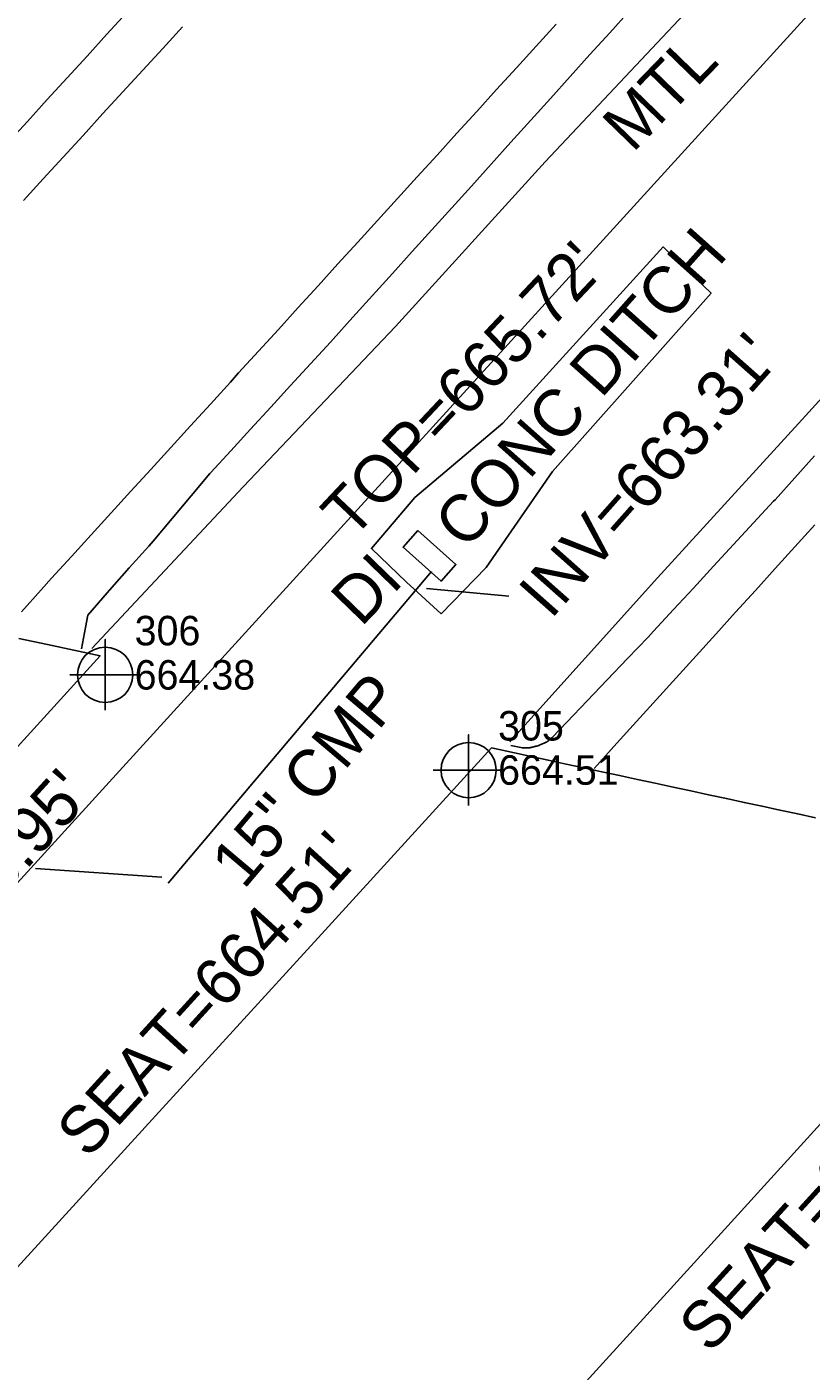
# Model space of a CAD drawing. Extents: x 1806071 to 1809844, y 912722 to 917035.
# Drawn here: x 1809158.4 to 1809224.9, y 916067.4 to 916181.4 of the extents above; entities that cross this region are included whole.
import ezdxf

# ---------------------------------------------------------------- set-up
doc = ezdxf.new("R2010")
doc.units = 0
for name, color, linetype in [('Exist Guardrail', 7, 'Continuous'), ('Exist Guardrail Text', 7, 'Continuous'), ('Exist Horizontal Alignment', 7, 'Continuous'), ('Exist Roads EOP', 7, 'Continuous'), ('Exist Roads EOT', 7, 'Continuous'), ('Exist Structure Major Bridge Seat Cogo Elevation', 7, 'Continuous'), ('Exist Structure Major Bridge Seat Cogo Number', 7, 'Continuous'), ('Exist Structure Major Bridge Seat Cogo Point CELL', 7, 'Continuous'), ('Exist Structure Major Bridge Seat Top Elevation', 7, 'Continuous'), ('Exist Structure Major Deck Tunnel Box Culvert', 7, 'Continuous'), ('Exist Structure Minor Drop Inlet', 7, 'Continuous'), ('Exist Structure Minor Drop Inlet Text', 7, 'Continuous'), ('Exist Structure Minor Drop Inlet Top Elevation', 7, 'Continuous'), ('Exist Structure Minor Paved Ditch or Gutter', 7, 'Continuous'), ('Exist Structure Minor Paved Ditch or Gutter Text', 7, 'Continuous'), ('Exist Structure Minor Pipes CMP 15 Inch', 7, 'Continuous'), ('Exist Structure Minor Pipes CMP 15 Inch Invert', 7, 'Continuous'), ('Exist Structure Minor Pipes CMP 15 Inch Text', 7, 'Continuous')]:
    doc.layers.add(name, color=color, linetype=linetype)

msp = doc.modelspace()

# ---------------------------------------------------------------- linework, layer by layer
at = {"layer": 'Exist Guardrail'}
for points in [[(1809223.66, 916192.6), (1809202.38, 916169.96), (1809189.69, 916156.01), (1809176.75, 916142.41), (1809163.93, 916128.69)], [(1809199.38, 916120.79), (1809211.9, 916134.7), (1809224.46, 916148.44), (1809245.44, 916171.5)]]:
    msp.add_lwpolyline(points, dxfattribs=at)
at = {"layer": 'Exist Horizontal Alignment'}
msp.add_line((1806073.69, 912724.84), (1809374.2, 916346.52), dxfattribs=at)
at = {"layer": 'Exist Roads EOP'}
for points in [[(1809166.88, 916182.62), (1809165.19, 916180.78), (1809163.51, 916178.93), (1809161.82, 916177.08), (1809160.14, 916175.24), (1809158.45, 916173.39), (1809156.76, 916171.55)], [(1809163.05, 916128.67), (1809163.39, 916130.49), (1809163.59, 916131.52), (1809165.21, 916133.42), (1809165.42, 916133.66), (1809167.09, 916135.53), (1809168.76, 916137.39), (1809169.13, 916137.8), (1809170.73, 916139.72), (1809172.34, 916141.64), (1809173.94, 916143.55), (1809174.01, 916143.63), (1809175.7, 916145.47), (1809177.39, 916147.31), (1809179.09, 916149.15), (1809180.78, 916150.99), (1809182.47, 916152.83), (1809184.16, 916154.67), (1809184.39, 916154.93), (1809186.07, 916156.78), (1809187.74, 916158.64), (1809189.42, 916160.49), (1809191.09, 916162.35), (1809192.77, 916164.2), (1809194.45, 916166.06), (1809196.12, 916167.91), (1809197.8, 916169.77), (1809199.47, 916171.63), (1809201.15, 916173.48), (1809202.82, 916175.34), (1809204.5, 916177.19), (1809206.17, 916179.05), (1809207.85, 916180.9), (1809209.52, 916182.76)], [(1809225.22, 916145.04), (1809223.54, 916143.18), (1809221.87, 916141.32), (1809221.74, 916141.18), (1809220.05, 916139.35), (1809218.35, 916137.51), (1809216.66, 916135.67), (1809214.96, 916133.83), (1809213.27, 916132), (1809211.57, 916130.16), (1809211.1, 916129.65), (1809209.37, 916127.85), (1809207.64, 916126.04), (1809205.94, 916124.27), (1809204.22, 916122.46), (1809202.96, 916121.15), (1809202.95, 916121.14), (1809202.95, 916121.14), (1809202.95, 916121.14), (1809202.94, 916121.13), (1809202.94, 916121.13), (1809202.93, 916121.13), (1809202.93, 916121.13), (1809202.93, 916121.12), (1809202.92, 916121.12), (1809202.92, 916121.12), (1809202.92, 916121.11), (1809202.91, 916121.11), (1809202.91, 916121.11), (1809202.91, 916121.1), (1809202.9, 916121.1), (1809202.9, 916121.1), (1809202.89, 916121.09), (1809202.89, 916121.09), (1809202.89, 916121.09), (1809202.88, 916121.09), (1809202.88, 916121.08), (1809202.88, 916121.08), (1809202.87, 916121.08), (1809202.87, 916121.07), (1809202.87, 916121.07), (1809202.86, 916121.07), (1809202.86, 916121.06), (1809202.85, 916121.06), (1809202.85, 916121.06), (1809202.85, 916121.05), (1809202.84, 916121.05), (1809202.84, 916121.05), (1809202.84, 916121.05), (1809202.83, 916121.04), (1809202.83, 916121.04), (1809202.82, 916121.04), (1809202.82, 916121.03), (1809202.82, 916121.03), (1809202.81, 916121.03), (1809202.81, 916121.02), (1809202.81, 916121.02), (1809202.8, 916121.02), (1809202.8, 916121.01), (1809202.8, 916121.01), (1809202.79, 916121.01), (1809202.79, 916121.01), (1809202.78, 916121), (1809202.78, 916121), (1809202.78, 916121), (1809202.77, 916120.99), (1809202.77, 916120.99), (1809202.77, 916120.99), (1809202.76, 916120.98), (1809202.76, 916120.98), (1809202.75, 916120.98), (1809202.75, 916120.98), (1809202.75, 916120.97), (1809202.74, 916120.97), (1809202.74, 916120.97), (1809202.74, 916120.96), (1809202.73, 916120.96), (1809202.73, 916120.96), (1809202.73, 916120.95), (1809202.72, 916120.95), (1809202.72, 916120.95), (1809202.71, 916120.94), (1809202.71, 916120.94), (1809202.71, 916120.94), (1809202.7, 916120.94), (1809202.7, 916120.93), (1809202.7, 916120.93), (1809202.69, 916120.93), (1809202.69, 916120.92), (1809202.68, 916120.92), (1809202.68, 916120.92), (1809202.68, 916120.91), (1809202.67, 916120.91), (1809202.67, 916120.91), (1809202.67, 916120.9), (1809202.66, 916120.9), (1809202.66, 916120.9), (1809202.66, 916120.9), (1809202.65, 916120.89), (1809202.65, 916120.89), (1809202.64, 916120.89), (1809202.64, 916120.88), (1809202.64, 916120.88), (1809202.63, 916120.88), (1809202.63, 916120.87), (1809202.63, 916120.87), (1809202.62, 916120.87), (1809202.62, 916120.86), (1809202.62, 916120.86), (1809202.61, 916120.86), (1809202.61, 916120.86), (1809202.6, 916120.85), (1809202.6, 916120.85), (1809202.6, 916120.85), (1809202.59, 916120.84), (1809202.59, 916120.84), (1809202.59, 916120.84), (1809202.58, 916120.83), (1809202.58, 916120.83), (1809202.57, 916120.83), (1809202.57, 916120.83), (1809202.57, 916120.82), (1809202.56, 916120.82), (1809202.56, 916120.82), (1809202.56, 916120.81), (1809202.55, 916120.81), (1809202.55, 916120.81), (1809202.55, 916120.8), (1809202.54, 916120.8), (1809202.54, 916120.8), (1809202.53, 916120.79), (1809202.53, 916120.79), (1809202.53, 916120.79), (1809202.52, 916120.79), (1809202.52, 916120.78), (1809202.52, 916120.78), (1809202.51, 916120.78), (1809202.51, 916120.77), (1809202.5, 916120.77), (1809202.49, 916120.77), (1809202.49, 916120.77), (1809202.48, 916120.76), (1809202.47, 916120.76), (1809202.47, 916120.76), (1809202.46, 916120.75), (1809202.46, 916120.75), (1809202.45, 916120.75), (1809202.44, 916120.75), (1809202.44, 916120.74), (1809202.43, 916120.74), (1809202.42, 916120.74), (1809202.42, 916120.74), (1809202.41, 916120.73), (1809202.4, 916120.73), (1809202.4, 916120.73), (1809202.39, 916120.73), (1809202.39, 916120.72), (1809202.38, 916120.72), (1809202.37, 916120.72), (1809202.37, 916120.71), (1809202.36, 916120.71), (1809202.35, 916120.71), (1809202.35, 916120.71), (1809202.34, 916120.7), (1809202.33, 916120.7), (1809202.33, 916120.7), (1809202.32, 916120.7), (1809202.31, 916120.69), (1809202.31, 916120.69), (1809202.3, 916120.69), (1809202.3, 916120.68), (1809202.29, 916120.68), (1809202.28, 916120.68), (1809202.28, 916120.68), (1809202.27, 916120.67), (1809202.26, 916120.67), (1809202.26, 916120.67), (1809202.25, 916120.67), (1809202.24, 916120.66), (1809202.24, 916120.66), (1809202.23, 916120.66), (1809202.23, 916120.65), (1809202.22, 916120.65), (1809202.21, 916120.65), (1809202.21, 916120.65), (1809202.2, 916120.64), (1809202.19, 916120.64), (1809202.19, 916120.64), (1809202.18, 916120.64), (1809202.17, 916120.63), (1809202.17, 916120.63), (1809202.16, 916120.63), (1809202.16, 916120.62), (1809202.15, 916120.62), (1809202.14, 916120.62), (1809202.14, 916120.62), (1809202.13, 916120.61), (1809202.12, 916120.61), (1809202.12, 916120.61), (1809202.11, 916120.61), (1809202.1, 916120.6), (1809202.1, 916120.6), (1809202.09, 916120.6), (1809202.08, 916120.59), (1809202.08, 916120.59), (1809202.07, 916120.59), (1809202.07, 916120.59), (1809202.06, 916120.58), (1809202.05, 916120.58), (1809202.05, 916120.58), (1809202.04, 916120.58), (1809202.03, 916120.57), (1809202.03, 916120.57), (1809202.02, 916120.57), (1809202.01, 916120.56), (1809202.01, 916120.56), (1809202, 916120.56), (1809202, 916120.56), (1809201.99, 916120.55), (1809201.98, 916120.55), (1809201.98, 916120.55), (1809201.97, 916120.55), (1809201.96, 916120.54), (1809201.96, 916120.54), (1809201.95, 916120.54), (1809201.94, 916120.53), (1809201.94, 916120.53), (1809201.93, 916120.53), (1809201.93, 916120.53), (1809201.92, 916120.52), (1809201.91, 916120.52), (1809201.91, 916120.52), (1809201.9, 916120.52), (1809201.89, 916120.51), (1809201.89, 916120.51), (1809201.88, 916120.51), (1809201.87, 916120.5), (1809201.87, 916120.5), (1809201.86, 916120.5), (1809201.85, 916120.5), (1809201.85, 916120.49), (1809201.84, 916120.49), (1809201.84, 916120.49), (1809201.83, 916120.49), (1809201.82, 916120.48), (1809201.82, 916120.48), (1809201.81, 916120.48), (1809201.8, 916120.48), (1809201.8, 916120.47), (1809201.79, 916120.47), (1809201.78, 916120.47), (1809201.78, 916120.46), (1809201.77, 916120.46), (1809201.77, 916120.46), (1809201.76, 916120.46), (1809201.75, 916120.45), (1809201.75, 916120.45), (1809201.74, 916120.45), (1809201.74, 916120.45), (1809201.73, 916120.45), (1809201.72, 916120.44), (1809201.72, 916120.44), (1809201.71, 916120.44), (1809201.71, 916120.44), (1809201.7, 916120.44), (1809201.7, 916120.44), (1809201.69, 916120.44), (1809201.68, 916120.43), (1809201.68, 916120.43), (1809201.67, 916120.43), (1809201.67, 916120.43), (1809201.66, 916120.43), (1809201.65, 916120.43), (1809201.65, 916120.43), (1809201.64, 916120.43), (1809201.64, 916120.42), (1809201.63, 916120.42), (1809201.63, 916120.42), (1809201.62, 916120.42), (1809201.61, 916120.42), (1809201.61, 916120.42), (1809201.6, 916120.42), (1809201.6, 916120.41), (1809201.59, 916120.41), (1809201.59, 916120.41), (1809201.58, 916120.41), (1809201.57, 916120.41), (1809201.57, 916120.41), (1809201.56, 916120.41), (1809201.56, 916120.4), (1809201.55, 916120.4), (1809201.55, 916120.4), (1809201.54, 916120.4), (1809201.53, 916120.4), (1809201.53, 916120.4), (1809201.52, 916120.4), (1809201.52, 916120.4), (1809201.51, 916120.39), (1809201.51, 916120.39), (1809201.5, 916120.39), (1809201.49, 916120.39), (1809201.49, 916120.39), (1809201.48, 916120.39), (1809201.48, 916120.39), (1809201.47, 916120.38), (1809201.46, 916120.38), (1809201.46, 916120.38), (1809201.45, 916120.38), (1809201.45, 916120.38), (1809201.44, 916120.38), (1809201.44, 916120.38), (1809201.43, 916120.37), (1809201.42, 916120.37), (1809201.42, 916120.37), (1809201.41, 916120.37), (1809201.41, 916120.37), (1809201.4, 916120.37), (1809201.4, 916120.37), (1809201.39, 916120.37), (1809201.38, 916120.36), (1809201.38, 916120.36), (1809201.37, 916120.36), (1809201.37, 916120.36), (1809201.36, 916120.36), (1809201.36, 916120.36), (1809201.35, 916120.36), (1809201.34, 916120.35), (1809201.34, 916120.35), (1809201.33, 916120.35), (1809201.33, 916120.35), (1809201.32, 916120.35), (1809201.31, 916120.35), (1809201.31, 916120.35), (1809201.3, 916120.34), (1809201.3, 916120.34), (1809201.29, 916120.34), (1809201.29, 916120.34), (1809201.28, 916120.34), (1809201.27, 916120.34), (1809201.27, 916120.34), (1809201.26, 916120.34), (1809201.26, 916120.33), (1809201.25, 916120.33), (1809201.25, 916120.33), (1809201.24, 916120.33), (1809201.23, 916120.33), (1809201.23, 916120.33), (1809201.22, 916120.33), (1809201.22, 916120.32), (1809201.21, 916120.32), (1809201.21, 916120.32), (1809201.2, 916120.32), (1809201.19, 916120.32), (1809201.19, 916120.32), (1809201.18, 916120.32), (1809201.18, 916120.31), (1809201.17, 916120.31), (1809201.17, 916120.31), (1809201.16, 916120.31), (1809201.15, 916120.31), (1809201.15, 916120.31), (1809201.14, 916120.31), (1809201.14, 916120.3), (1809201.13, 916120.3), (1809201.12, 916120.3), (1809201.12, 916120.3), (1809201.11, 916120.3), (1809201.11, 916120.3), (1809201.1, 916120.3), (1809201.1, 916120.3), (1809201.09, 916120.29), (1809201.08, 916120.29), (1809201.08, 916120.29), (1809201.07, 916120.29), (1809201.07, 916120.29), (1809201.06, 916120.29), (1809201.06, 916120.29), (1809201.05, 916120.28), (1809201.05, 916120.28), (1809201.04, 916120.28), (1809201.04, 916120.28), (1809201.03, 916120.28), (1809201.03, 916120.28), (1809201.02, 916120.28), (1809201.02, 916120.28), (1809201.01, 916120.28), (1809201.01, 916120.28), (1809201, 916120.28), (1809201, 916120.28), (1809200.99, 916120.28), (1809200.99, 916120.28), (1809200.98, 916120.28), (1809200.98, 916120.28), (1809200.97, 916120.28), (1809200.97, 916120.28), (1809200.96, 916120.28), (1809200.96, 916120.28), (1809200.95, 916120.28), (1809200.95, 916120.28), (1809200.94, 916120.28), (1809200.94, 916120.28), (1809200.93, 916120.28), (1809200.93, 916120.28), (1809200.92, 916120.28), (1809200.92, 916120.28), (1809200.91, 916120.28), (1809200.9, 916120.28), (1809200.9, 916120.28), (1809200.89, 916120.28), (1809200.89, 916120.28), (1809200.88, 916120.28), (1809200.88, 916120.28), (1809200.87, 916120.28), (1809200.87, 916120.28), (1809200.86, 916120.28), (1809200.86, 916120.28), (1809200.85, 916120.28), (1809200.85, 916120.28), (1809200.84, 916120.28), (1809200.84, 916120.28), (1809200.83, 916120.28), (1809200.83, 916120.28), (1809200.82, 916120.28), (1809200.82, 916120.28), (1809200.81, 916120.28), (1809200.81, 916120.28), (1809200.8, 916120.28), (1809200.8, 916120.28), (1809200.79, 916120.28), (1809200.79, 916120.28), (1809200.78, 916120.28), (1809200.78, 916120.28), (1809200.77, 916120.28), (1809200.77, 916120.28), (1809200.75, 916120.28), (1809200.74, 916120.28), (1809200.74, 916120.28), (1809200.73, 916120.28), (1809200.73, 916120.28), (1809200.72, 916120.28), (1809200.72, 916120.28), (1809200.71, 916120.28), (1809200.71, 916120.28), (1809200.7, 916120.28), (1809200.7, 916120.28), (1809200.69, 916120.28), (1809200.69, 916120.28), (1809200.68, 916120.28), (1809200.68, 916120.28), (1809200.67, 916120.28), (1809200.67, 916120.28), (1809200.66, 916120.28), (1809200.66, 916120.28), (1809200.65, 916120.28), (1809200.65, 916120.28), (1809200.64, 916120.28), (1809200.64, 916120.28), (1809200.63, 916120.28), (1809200.63, 916120.28), (1809200.62, 916120.28), (1809200.62, 916120.28), (1809200.61, 916120.28), (1809200.61, 916120.28), (1809200.6, 916120.28), (1809200.6, 916120.28), (1809200.59, 916120.28), (1809200.59, 916120.28), (1809200.58, 916120.27), (1809200.58, 916120.27), (1809200.57, 916120.27), (1809200.57, 916120.27), (1809200.56, 916120.27), (1809200.56, 916120.27), (1809200.55, 916120.27), (1809200.55, 916120.27), (1809200.54, 916120.27), (1809200.54, 916120.27), (1809200.53, 916120.27), (1809200.53, 916120.27), (1809200.52, 916120.27), (1809200.51, 916120.27), (1809200.51, 916120.27), (1809200.5, 916120.27), (1809200.5, 916120.27), (1809200.49, 916120.27), (1809200.49, 916120.27), (1809200.48, 916120.27), (1809200.48, 916120.27), (1809200.47, 916120.27), (1809200.47, 916120.27), (1809200.46, 916120.27), (1809200.45, 916120.27), (1809200.45, 916120.27), (1809200.44, 916120.27), (1809199.46, 916120.48)]]:
    msp.add_lwpolyline(points, dxfattribs=at)
at = {"layer": 'Exist Roads EOT'}
for points in [[(1809157.95, 916131.8), (1809159.62, 916133.67), (1809160.5, 916134.66), (1809162.19, 916136.5), (1809163.87, 916138.35), (1809165.56, 916140.2), (1809167.24, 916142.04), (1809168.93, 916143.89), (1809170.61, 916145.74), (1809172.3, 916147.59), (1809173.98, 916149.43), (1809175.67, 916151.28), (1809176.37, 916152.06), (1809178.06, 916153.9), (1809179.74, 916155.75), (1809181.42, 916157.6), (1809183.11, 916159.45), (1809184.79, 916161.3), (1809186.47, 916163.15), (1809188.16, 916165), (1809189.84, 916166.84), (1809191.52, 916168.69), (1809193.21, 916170.54), (1809194.89, 916172.39), (1809196.57, 916174.24), (1809198.25, 916176.09), (1809199.94, 916177.94), (1809201.62, 916179.78), (1809203.3, 916181.63)], [(1809171.62, 916181.42), (1809169.93, 916179.58), (1809168.24, 916177.73), (1809166.55, 916175.89), (1809164.86, 916174.05), (1809163.17, 916172.2), (1809161.48, 916170.36), (1809159.79, 916168.52), (1809158.11, 916166.67)], [(1809225.24, 916139.19), (1809223.56, 916137.33), (1809221.88, 916135.48), (1809220.2, 916133.63), (1809218.53, 916131.78), (1809216.85, 916129.93), (1809215.17, 916128.07), (1809213.49, 916126.22), (1809211.81, 916124.37), (1809210.13, 916122.52), (1809208.45, 916120.67), (1809206.77, 916118.81), (1809206.52, 916118.54)]]:
    msp.add_lwpolyline(points, dxfattribs=at)
at = {"layer": 'Exist Structure Major Bridge Seat Cogo Point CELL'}
for points in [[(1809162.05, 916126.47), (1809168.05, 916126.47), (1809165.05, 916126.47), (1809165.05, 916129.47), (1809165.05, 916123.47)], [(1809192.88, 916118.39), (1809198.88, 916118.39), (1809195.88, 916118.39), (1809195.88, 916121.39), (1809195.88, 916115.39)]]:
    msp.add_lwpolyline(points, dxfattribs=at)
for centre in [(1809165.05, 916126.47), (1809195.88, 916118.39)]:
    msp.add_circle(centre, 2.34, dxfattribs=at)
at = {"layer": 'Exist Structure Major Deck Tunnel Box Culvert'}
for points in [[(1809157.72, 916129.56), (1809160.17, 916129.04), (1809164.62, 916128.09), (1809164.62, 916128.09), (1809151.1, 916113.25)], [(1809156.43, 916074.95), (1809169.92, 916089.72), (1809183.4, 916104.49), (1809197.82, 916120.27), (1809202.64, 916119.24), (1809204.15, 916118.91), (1809205.66, 916118.59), (1809207.17, 916118.26), (1809208.69, 916117.94), (1809210.2, 916117.61), (1809211.71, 916117.28), (1809213.22, 916116.96), (1809214.73, 916116.63), (1809216.24, 916116.31), (1809217.75, 916115.98), (1809219.26, 916115.66), (1809220.77, 916115.33), (1809222.29, 916115.01), (1809223.8, 916114.68), (1809225.31, 916114.36)], [(1809231.61, 916094.87), (1809218.15, 916080.08), (1809204.68, 916065.29)]]:
    msp.add_lwpolyline(points, dxfattribs=at)
at = {"layer": 'Exist Structure Minor Drop Inlet'}
msp.add_lwpolyline([(1809191.57, 916138.7), (1809194.8, 916135.81), (1809193.55, 916134.41), (1809190.32, 916137.29)], close=True, dxfattribs=at)
at = {"layer": 'Exist Structure Minor Paved Ditch or Gutter'}
for points in [[(1809191.33, 916141.51), (1809198.79, 916147.82), (1809212.38, 916162.75), (1809214.42, 916160.79)], [(1809214.42, 916160.79), (1809216.44, 916158.82), (1809202.99, 916143.71), (1809197.36, 916135.58)], [(1809193.55, 916131.65), (1809190.62, 916134.34), (1809187.64, 916137.17), (1809191.33, 916141.51)], [(1809197.36, 916135.58), (1809193.55, 916131.65)]]:
    msp.add_lwpolyline(points, dxfattribs=at)
at = {"layer": 'Exist Structure Minor Pipes CMP 15 Inch'}
msp.add_line((1809192.73, 916135.24), (1809170.4, 916108.82), dxfattribs=at)
at = {"layer": 'Exist Structure Minor Pipes CMP 15 Inch Invert'}
for p, q in [((1809192.31, 916133.79), (1809199.3, 916133.14)), ((1809169.86, 916109.31), (1809159.14, 916110.06))]:
    msp.add_line(p, q, dxfattribs=at)

# ---------------------------------------------------------------- texts
at = {"layer": 'Exist Guardrail Text'}
msp.add_text('MTL', height=4, rotation=45.9035, dxfattribs=at).set_placement((1809209.8, 916170.66))
at = {"layer": 'Exist Structure Major Bridge Seat Cogo Elevation'}
for s, p in [('664.38', (1809167.55, 916125.22)), ('664.51', (1809198.38, 916117.15))]:
    msp.add_text(s, height=2.5, dxfattribs=at).set_placement(p)
at = {"layer": 'Exist Structure Major Bridge Seat Cogo Number'}
for s, p in [('306', (1809167.55, 916128.97)), ('305', (1809198.38, 916120.9))]:
    msp.add_text(s, height=2.5, dxfattribs=at).set_placement(p)
at = {"layer": 'Exist Structure Major Bridge Seat Top Elevation'}
for s, p in [("SEAT=664.51'", (1809163.59, 916085.35)), ("SEAT=664.08'", (1809216.35, 916068.82))]:
    msp.add_text(s, height=4, rotation=47.6571, dxfattribs=at).set_placement(p)
at = {"layer": 'Exist Structure Minor Drop Inlet Text'}
msp.add_text('DI', height=4, rotation=45.911, dxfattribs=at).set_placement((1809186.76, 916130.46))
at = {"layer": 'Exist Structure Minor Drop Inlet Top Elevation'}
msp.add_text("TOP=665.72'", height=4, rotation=46.6654, dxfattribs=at).set_placement((1809186, 916137.86))
at = {"layer": 'Exist Structure Minor Paved Ditch or Gutter Text'}
msp.add_text('CONC DITCH', height=4, rotation=48.3425, dxfattribs=at).set_placement((1809195.67, 916136.95))
at = {"layer": 'Exist Structure Minor Pipes CMP 15 Inch Invert'}
for s, rotation, p in [("INV=663.31'", 48.4645, (1809202.86, 916131.1)), ("INV=656.95'", 47.5847, (1809144.16, 916094.37))]:
    msp.add_text(s, height=4, rotation=rotation, dxfattribs=at).set_placement(p)
at = {"layer": 'Exist Structure Minor Pipes CMP 15 Inch Text'}
msp.add_text('15" CMP', height=4, rotation=49.8002, dxfattribs=at).set_placement((1809176.81, 916108.19))

doc.saveas('drawing.dxf')
